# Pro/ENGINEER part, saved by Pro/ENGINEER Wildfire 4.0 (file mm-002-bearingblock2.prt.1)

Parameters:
  METRIC = "NO"

Other parameters: PITCH, DRILL_POINT_ANGLE, DRILL_DEPTH, DRILL_DIAMETER, THREAD_DIAMETER, THREADS_PER_INCH, THREAD_DEPTH, THREAD_LENGTH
